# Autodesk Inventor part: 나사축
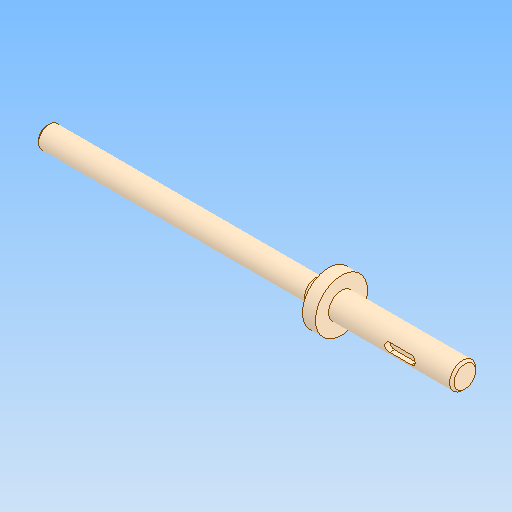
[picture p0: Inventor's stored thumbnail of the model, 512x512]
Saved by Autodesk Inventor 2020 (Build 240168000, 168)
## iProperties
Created: 2024-07
Part Number: 나사축
Material: 강철, 연강
Document SubType Name: Modeling
Designer: oem
Density: 7.86 g/cm^3
Appearance: 기본값
Author: jhkim
Sending System: Autodesk Inventor 2025
Preprocessor: ST-DEVELOPER v20
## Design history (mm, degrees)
feature "솔리드1"
node "솔리드2"
